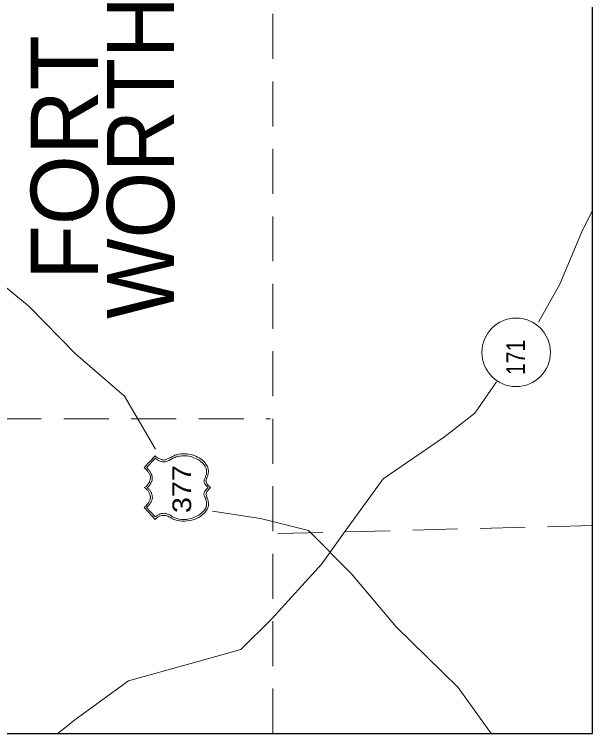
# Model space of a CAD drawing. Extents: x 2363323 to 2367082, y 6956018 to 6980837.
# Drawn here: x 2366061.2 to 2366219.2, y 6980386 to 6980582.6 of the extents above; entities that cross this region are included whole.
import ezdxf

# ---------------------------------------------------------------- set-up
doc = ezdxf.new("R2010")
doc.units = 0
doc.header["$LTSCALE"] = 4.1
doc.linetypes.add('MEDIUM_DASHED', pattern=[4.5, 3, -1.5])
doc.layers.add('62', color=7, linetype='Continuous', lineweight=13)
doc.layers.add('63', color=7, linetype='Continuous', lineweight=13)

msp = doc.modelspace()

# ---------------------------------------------------------------- linework, layer by layer
at = {"layer": '62', "linetype": 'MEDIUM_DASHED'}
for p, q in [((2366131.806, 6980385.954), (2366131.805, 6980835.548)), ((2365945.536, 6980472.004), (2366131.242, 6980472.027)), ((2366219.249, 6980442.84), (2366131.536, 6980440.635))]:
    msp.add_line(p, q, dxfattribs=at)
at = {"layer": '62'}
for p, q in [((2366078.927, 6980528.37), (2366076.924, 6980526.212)), ((2366210.249, 6980508.837), (2366204.468, 6980498.445)), ((2366187.026, 6980473.6), (2366193.011, 6980482.15)), ((2366091.302, 6980478.192), (2366099.784, 6980463.723)), ((2366178.768, 6980467.12), (2366187.026, 6980473.6))]:
    msp.add_line(p, q, dxfattribs=at)
at = {"layer": '62', "lineweight": 25}
msp.add_lwpolyline([(2365753.976, 6980385.954), (2366219.249, 6980385.954), (2366219.249, 6980835.546), (2365753.974, 6980835.546)], dxfattribs=at)
at = {"layer": '62'}
for points in [[(2366210.249, 6980508.837), (2366216.459, 6980523.668), (2366219.25, 6980528.978)], [(2366049.676, 6980516.892), (2366057.932, 6980508.726), (2366065.266, 6980502.741), (2366077.871, 6980489.824), (2366091.302, 6980478.192)], [(2366073.1, 6980385.956), (2366077.691, 6980389.758), (2366092.384, 6980400.357), (2366109.395, 6980405.127), (2366123.12, 6980408.93), (2366131.512, 6980417.21), (2366145.197, 6980432.422), (2366151.61, 6980441.355), (2366162.004, 6980455.598), (2366178.768, 6980467.12)], [(2366099.672, 6980444.528), (2366096.68, 6980447.79), (2366096.861, 6980447.97), (2366097.086, 6980448.172), (2366097.242, 6980448.352), (2366097.401, 6980448.532), (2366097.558, 6980448.712), (2366097.694, 6980448.915), (2366097.827, 6980449.095), (2366097.964, 6980449.275), (2366098.054, 6980449.455), (2366098.142, 6980449.635), (2366098.232, 6980449.836), (2366098.277, 6980450.018), (2366098.322, 6980450.22), (2366098.366, 6980450.378), (2366098.368, 6980450.58), (2366098.367, 6980450.782), (2366098.322, 6980450.918), (2366098.277, 6980451.075), (2366098.254, 6980451.255), (2366098.21, 6980451.435), (2366098.12, 6980451.616), (2366098.052, 6980451.795), (2366097.964, 6980451.952), (2366097.874, 6980452.132), (2366097.737, 6980452.314), (2366097.624, 6980452.472), (2366097.467, 6980452.628), (2366097.354, 6980452.785), (2366097.198, 6980452.922), (2366097.04, 6980453.032), (2366096.861, 6980453.122), (2366096.68, 6980453.214), (2366096.861, 6980453.325), (2366097.04, 6980453.46), (2366097.22, 6980453.572), (2366097.356, 6980453.732), (2366097.514, 6980453.866), (2366097.647, 6980454.045), (2366097.784, 6980454.225), (2366097.896, 6980454.382), (2366097.984, 6980454.564), (2366098.098, 6980454.746), (2366098.164, 6980454.948), (2366098.234, 6980455.126), (2366098.277, 6980455.353), (2366098.324, 6980455.509), (2366098.367, 6980455.734), (2366098.391, 6980455.936), (2366098.39, 6980456.094), (2366098.367, 6980456.272), (2366098.324, 6980456.43), (2366098.278, 6980456.636), (2366098.188, 6980456.792), (2366098.098, 6980456.972), (2366098.007, 6980457.13), (2366097.894, 6980457.309), (2366097.782, 6980457.465), (2366097.647, 6980457.67), (2366097.512, 6980457.828), (2366097.356, 6980458.005), (2366097.197, 6980458.166), (2366097.017, 6980458.366), (2366096.861, 6980458.502), (2366096.681, 6980458.682), (2366099.672, 6980461.946), (2366099.988, 6980461.652), (2366100.324, 6980461.359), (2366100.707, 6980461.156), (2366101.091, 6980460.999), (2366101.474, 6980460.864), (2366101.834, 6980460.796), (2366102.104, 6980460.774), (2366102.328, 6980460.798), (2366102.486, 6980460.82), (2366102.69, 6980460.91), (2366102.867, 6980460.976), (2366103.095, 6980461.066), (2366103.322, 6980461.179), (2366103.545, 6980461.293), (2366103.792, 6980461.406), (2366104.04, 6980461.539), (2366104.312, 6980461.674), (2366104.558, 6980461.81), (2366104.852, 6980461.944), (2366105.098, 6980462.056), (2366105.345, 6980462.146), (2366105.615, 6980462.214), (2366105.864, 6980462.304), (2366106.112, 6980462.326), (2366106.695, 6980462.418), (2366107.236, 6980462.462), (2366107.775, 6980462.462), (2366108.315, 6980462.416), (2366108.834, 6980462.372), (2366109.35, 6980462.258), (2366109.821, 6980462.146), (2366110.318, 6980461.988), (2366110.792, 6980461.809), (2366111.264, 6980461.584)], [(2366112.052, 6980460.414), (2366111.802, 6980460.594), (2366111.51, 6980460.795), (2366111.172, 6980460.976), (2366110.859, 6980461.134), (2366110.475, 6980461.292), (2366110.094, 6980461.449), (2366109.712, 6980461.606), (2366109.282, 6980461.719), (2366108.856, 6980461.809), (2366108.405, 6980461.876), (2366107.932, 6980461.944), (2366107.46, 6980461.942), (2366106.965, 6980461.899), (2366106.538, 6980461.852), (2366106.156, 6980461.809), (2366105.796, 6980461.719), (2366105.459, 6980461.629), (2366105.122, 6980461.496), (2366104.828, 6980461.359), (2366104.535, 6980461.246), (2366104.265, 6980461.089), (2366103.995, 6980460.909), (2366103.772, 6980460.796), (2366103.524, 6980460.662), (2366103.276, 6980460.549), (2366103.028, 6980460.436), (2366102.778, 6980460.369), (2366102.531, 6980460.302), (2366102.261, 6980460.256), (2366101.946, 6980460.256), (2366101.607, 6980460.302), (2366101.27, 6980460.369), (2366100.932, 6980460.459), (2366100.596, 6980460.596), (2366100.281, 6980460.796), (2366099.987, 6980461), (2366099.696, 6980461.248), (2366097.288, 6980458.659), (2366097.468, 6980458.502), (2366097.626, 6980458.366), (2366097.782, 6980458.209), (2366097.94, 6980458.052), (2366098.076, 6980457.873), (2366098.211, 6980457.692), (2366098.322, 6980457.513), (2366098.434, 6980457.332), (2366098.524, 6980457.129), (2366098.637, 6980456.949), (2366098.706, 6980456.746), (2366098.751, 6980456.589), (2366098.817, 6980456.388), (2366098.841, 6980456.229), (2366098.862, 6980456.094), (2366098.884, 6980455.935), (2366098.864, 6980455.779), (2366098.864, 6980455.576), (2366098.84, 6980455.396), (2366098.817, 6980455.216), (2366098.751, 6980455.014), (2366098.682, 6980454.856), (2366098.614, 6980454.654), (2366098.524, 6980454.474), (2366098.434, 6980454.316), (2366098.344, 6980454.112), (2366098.232, 6980453.956), (2366098.097, 6980453.798), (2366097.984, 6980453.618), (2366097.827, 6980453.505), (2366097.671, 6980453.348), (2366097.491, 6980453.212), (2366097.67, 6980453.078), (2366097.827, 6980452.965), (2366097.941, 6980452.808), (2366098.076, 6980452.674), (2366098.164, 6980452.538), (2366098.277, 6980452.404), (2366098.39, 6980452.222), (2366098.48, 6980452.108), (2366098.547, 6980451.93), (2366098.637, 6980451.772), (2366098.684, 6980451.616), (2366098.75, 6980451.458), (2366098.772, 6980451.298), (2366098.84, 6980451.144), (2366098.864, 6980450.964), (2366098.886, 6980450.805), (2366098.907, 6980450.625), (2366098.907, 6980450.4), (2366098.862, 6980450.22), (2366098.817, 6980449.996), (2366098.75, 6980449.794), (2366098.66, 6980449.568), (2366098.57, 6980449.365), (2366098.457, 6980449.185), (2366098.344, 6980448.982), (2366098.21, 6980448.759), (2366098.097, 6980448.578), (2366097.941, 6980448.42), (2366097.782, 6980448.218), (2366097.626, 6980448.06)], [(2366111.264, 6980461.584), (2366111.692, 6980461.36), (2366112.096, 6980461.066), (2366112.5, 6980460.776), (2366112.86, 6980460.414), (2366113.22, 6980460.054), (2366113.558, 6980459.672), (2366113.716, 6980459.446), (2366113.828, 6980459.244), (2366113.94, 6980458.996), (2366114.032, 6980458.772), (2366114.12, 6980458.569), (2366114.142, 6980458.344), (2366114.21, 6980458.096), (2366114.234, 6980457.894), (2366114.255, 6980457.669), (2366114.234, 6980457.444), (2366114.21, 6980457.242), (2366114.188, 6980457.04), (2366114.12, 6980456.814), (2366114.098, 6980456.656), (2366114.032, 6980456.454), (2366113.94, 6980456.274), (2366113.872, 6980456.116), (2366113.829, 6980455.938), (2366113.739, 6980455.78), (2366113.672, 6980455.623), (2366113.648, 6980455.464), (2366113.604, 6980455.306), (2366113.558, 6980455.126), (2366113.58, 6980454.946), (2366113.625, 6980454.766), (2366113.692, 6980454.586), (2366113.805, 6980454.382), (2366113.919, 6980454.202), (2366114.099, 6980453.955), (2366114.278, 6980453.73), (2366114.548, 6980453.505), (2366114.84, 6980453.212), (2366114.572, 6980452.965), (2366114.346, 6980452.718), (2366114.122, 6980452.515), (2366113.986, 6980452.312), (2366113.828, 6980452.132), (2366113.738, 6980451.954), (2366113.67, 6980451.795), (2366113.625, 6980451.638), (2366113.602, 6980451.525), (2366113.602, 6980451.346), (2366113.604, 6980451.232), (2366113.67, 6980451.075), (2366113.694, 6980450.94), (2366113.715, 6980450.805), (2366113.805, 6980450.649), (2366113.85, 6980450.488), (2366113.918, 6980450.378), (2366113.962, 6980450.198), (2366114.032, 6980450.018), (2366114.098, 6980449.839), (2366114.122, 6980449.635), (2366114.142, 6980449.455), (2366114.21, 6980449.252), (2366114.232, 6980449.052), (2366114.234, 6980448.825), (2366114.232, 6980448.645), (2366114.232, 6980448.42), (2366114.212, 6980448.172), (2366114.142, 6980447.97), (2366114.098, 6980447.745), (2366113.986, 6980447.52), (2366113.874, 6980447.296), (2366113.558, 6980446.778), (2366113.128, 6980446.282), (2366112.658, 6980445.832), (2366112.14, 6980445.428), (2366111.578, 6980445.068), (2366111.016, 6980444.775), (2366110.385, 6980444.55), (2366109.734, 6980444.348), (2366109.08, 6980444.214), (2366108.429, 6980444.122), (2366107.775, 6980444.055), (2366107.122, 6980444.056), (2366106.448, 6980444.122), (2366105.84, 6980444.235), (2366105.188, 6980444.415), (2366104.625, 6980444.638), (2366104.402, 6980444.73), (2366104.154, 6980444.842), (2366103.929, 6980444.976), (2366103.682, 6980445.135), (2366103.41, 6980445.248), (2366103.14, 6980445.382), (2366102.846, 6980445.518), (2366102.555, 6980445.585), (2366102.237, 6980445.63), (2366101.901, 6980445.63), (2366101.562, 6980445.632), (2366101.224, 6980445.518), (2366100.863, 6980445.405), (2366100.461, 6980445.202)], [(2366097.332, 6980447.792), (2366099.694, 6980445.225), (2366100.054, 6980445.518), (2366100.438, 6980445.72), (2366100.754, 6980445.9), (2366101.067, 6980446.035), (2366101.404, 6980446.125), (2366101.72, 6980446.17), (2366101.991, 6980446.215), (2366102.284, 6980446.172), (2366102.576, 6980446.126), (2366102.846, 6980446.058), (2366103.142, 6980445.968), (2366103.41, 6980445.855), (2366103.658, 6980445.742), (2366103.928, 6980445.584), (2366104.175, 6980445.429), (2366104.445, 6980445.27), (2366105.032, 6980444.978), (2366105.66, 6980444.776), (2366106.269, 6980444.618), (2366106.942, 6980444.55), (2366107.616, 6980444.528), (2366108.272, 6980444.55), (2366108.945, 6980444.661), (2366109.575, 6980444.818), (2366110.204, 6980445.022), (2366110.835, 6980445.294), (2366111.398, 6980445.584), (2366111.939, 6980445.945), (2366112.41, 6980446.328), (2366112.86, 6980446.754), (2366113.22, 6980447.229), (2366113.558, 6980447.722), (2366113.58, 6980447.836), (2366113.648, 6980447.949), (2366113.67, 6980448.104), (2366113.672, 6980448.285), (2366113.694, 6980448.442), (2366113.715, 6980448.6), (2366113.715, 6980448.782), (2366113.692, 6980448.982), (2366113.67, 6980449.164), (2366113.67, 6980449.342), (2366113.625, 6980449.524), (2366113.602, 6980449.702), (2366113.558, 6980449.882), (2366113.512, 6980450.04), (2366113.445, 6980450.198), (2366113.424, 6980450.332), (2366113.332, 6980450.49), (2366113.265, 6980450.625), (2366113.198, 6980450.76), (2366113.132, 6980450.896), (2366113.086, 6980451.075), (2366113.062, 6980451.188), (2366113.018, 6980451.345), (2366113.018, 6980451.526), (2366113.062, 6980451.682), (2366113.108, 6980451.885), (2366113.176, 6980452.065), (2366113.288, 6980452.224), (2366113.422, 6980452.449), (2366113.648, 6980452.674), (2366113.872, 6980452.942), (2366114.142, 6980453.19), (2366113.85, 6980453.505), (2366113.602, 6980453.776), (2366113.422, 6980454), (2366113.265, 6980454.248), (2366113.175, 6980454.472), (2366113.108, 6980454.652), (2366113.064, 6980454.856), (2366113.062, 6980455.058), (2366113.062, 6980455.239), (2366113.108, 6980455.396), (2366113.176, 6980455.576), (2366113.22, 6980455.756), (2366113.31, 6980455.936), (2366113.402, 6980456.116), (2366113.445, 6980456.296), (2366113.558, 6980456.498), (2366113.602, 6980456.702), (2366113.672, 6980456.928), (2366113.694, 6980457.129), (2366113.716, 6980457.33), (2366113.715, 6980457.556), (2366113.716, 6980457.782), (2366113.694, 6980457.986), (2366113.67, 6980458.209), (2366113.604, 6980458.434), (2366113.558, 6980458.638), (2366113.422, 6980458.84), (2366113.332, 6980459.064), (2366113.198, 6980459.246), (2366113.064, 6980459.469), (2366112.882, 6980459.672), (2366112.682, 6980459.874), (2366112.522, 6980460.056), (2366112.275, 6980460.213), (2366112.052, 6980460.414)], [(2366097.626, 6980448.06), (2366097.467, 6980447.925), (2366097.332, 6980447.792)], [(2366115.359, 6980446.8), (2366128.43, 6980444.822), (2366141.55, 6980441.49), (2366153.252, 6980429.766), (2366165.558, 6980415.117), (2366182.458, 6980398.58), (2366191.482, 6980385.954)], [(2366100.461, 6980445.202), (2366100.077, 6980444.912), (2366099.672, 6980444.528)]]:
    msp.add_lwpolyline(points, dxfattribs=at)
msp.add_circle((2366198.354, 6980490.209), 9.364, dxfattribs=at)
at = {"layer": '63', "linetype": 'MEDIUM_DASHED'}
for p, q in [((2366131.806, 6980385.954), (2366131.805, 6980835.548)), ((2365945.536, 6980472.004), (2366131.242, 6980472.027)), ((2366219.249, 6980442.84), (2366131.536, 6980440.635))]:
    msp.add_line(p, q, dxfattribs=at)
at = {"layer": '63'}
for p, q in [((2366078.927, 6980528.37), (2366076.924, 6980526.212)), ((2366210.249, 6980508.837), (2366204.468, 6980498.445)), ((2366187.026, 6980473.6), (2366193.011, 6980482.15)), ((2366091.302, 6980478.192), (2366099.784, 6980463.723)), ((2366178.768, 6980467.12), (2366187.026, 6980473.6))]:
    msp.add_line(p, q, dxfattribs=at)
at = {"layer": '63', "lineweight": 25}
msp.add_lwpolyline([(2365753.976, 6980385.954), (2366219.249, 6980385.954), (2366219.249, 6980835.546), (2365753.974, 6980835.546)], dxfattribs=at)
at = {"layer": '63'}
for points in [[(2366210.249, 6980508.837), (2366216.459, 6980523.668), (2366219.25, 6980528.978)], [(2366049.676, 6980516.892), (2366057.932, 6980508.726), (2366065.266, 6980502.741), (2366077.871, 6980489.824), (2366091.302, 6980478.192)], [(2366073.1, 6980385.956), (2366077.691, 6980389.758), (2366092.384, 6980400.357), (2366109.395, 6980405.127), (2366123.12, 6980408.93), (2366131.512, 6980417.21), (2366145.197, 6980432.422), (2366151.61, 6980441.355), (2366162.004, 6980455.598), (2366178.768, 6980467.12)], [(2366099.672, 6980444.528), (2366096.68, 6980447.79), (2366096.861, 6980447.97), (2366097.086, 6980448.172), (2366097.242, 6980448.352), (2366097.401, 6980448.532), (2366097.558, 6980448.712), (2366097.694, 6980448.915), (2366097.827, 6980449.095), (2366097.964, 6980449.275), (2366098.054, 6980449.455), (2366098.142, 6980449.635), (2366098.232, 6980449.836), (2366098.277, 6980450.018), (2366098.322, 6980450.22), (2366098.366, 6980450.378), (2366098.368, 6980450.58), (2366098.367, 6980450.782), (2366098.322, 6980450.918), (2366098.277, 6980451.075), (2366098.254, 6980451.255), (2366098.21, 6980451.435), (2366098.12, 6980451.616), (2366098.052, 6980451.795), (2366097.964, 6980451.952), (2366097.874, 6980452.132), (2366097.737, 6980452.314), (2366097.624, 6980452.472), (2366097.467, 6980452.628), (2366097.354, 6980452.785), (2366097.198, 6980452.922), (2366097.04, 6980453.032), (2366096.861, 6980453.122), (2366096.68, 6980453.214), (2366096.861, 6980453.325), (2366097.04, 6980453.46), (2366097.22, 6980453.572), (2366097.356, 6980453.732), (2366097.514, 6980453.866), (2366097.647, 6980454.045), (2366097.784, 6980454.225), (2366097.896, 6980454.382), (2366097.984, 6980454.564), (2366098.098, 6980454.746), (2366098.164, 6980454.948), (2366098.234, 6980455.126), (2366098.277, 6980455.353), (2366098.324, 6980455.509), (2366098.367, 6980455.734), (2366098.391, 6980455.936), (2366098.39, 6980456.094), (2366098.367, 6980456.272), (2366098.324, 6980456.43), (2366098.278, 6980456.636), (2366098.188, 6980456.792), (2366098.098, 6980456.972), (2366098.007, 6980457.13), (2366097.894, 6980457.309), (2366097.782, 6980457.465), (2366097.647, 6980457.67), (2366097.512, 6980457.828), (2366097.356, 6980458.005), (2366097.197, 6980458.166), (2366097.017, 6980458.366), (2366096.861, 6980458.502), (2366096.681, 6980458.682), (2366099.672, 6980461.946), (2366099.988, 6980461.652), (2366100.324, 6980461.359), (2366100.707, 6980461.156), (2366101.091, 6980460.999), (2366101.474, 6980460.864), (2366101.834, 6980460.796), (2366102.104, 6980460.774), (2366102.328, 6980460.798), (2366102.486, 6980460.82), (2366102.69, 6980460.91), (2366102.867, 6980460.976), (2366103.095, 6980461.066), (2366103.322, 6980461.179), (2366103.545, 6980461.293), (2366103.792, 6980461.406), (2366104.04, 6980461.539), (2366104.312, 6980461.674), (2366104.558, 6980461.81), (2366104.852, 6980461.944), (2366105.098, 6980462.056), (2366105.345, 6980462.146), (2366105.615, 6980462.214), (2366105.864, 6980462.304), (2366106.112, 6980462.326), (2366106.695, 6980462.418), (2366107.236, 6980462.462), (2366107.775, 6980462.462), (2366108.315, 6980462.416), (2366108.834, 6980462.372), (2366109.35, 6980462.258), (2366109.821, 6980462.146), (2366110.318, 6980461.988), (2366110.792, 6980461.809), (2366111.264, 6980461.584)], [(2366112.052, 6980460.414), (2366111.802, 6980460.594), (2366111.51, 6980460.795), (2366111.172, 6980460.976), (2366110.859, 6980461.134), (2366110.475, 6980461.292), (2366110.094, 6980461.449), (2366109.712, 6980461.606), (2366109.282, 6980461.719), (2366108.856, 6980461.809), (2366108.405, 6980461.876), (2366107.932, 6980461.944), (2366107.46, 6980461.942), (2366106.965, 6980461.899), (2366106.538, 6980461.852), (2366106.156, 6980461.809), (2366105.796, 6980461.719), (2366105.459, 6980461.629), (2366105.122, 6980461.496), (2366104.828, 6980461.359), (2366104.535, 6980461.246), (2366104.265, 6980461.089), (2366103.995, 6980460.909), (2366103.772, 6980460.796), (2366103.524, 6980460.662), (2366103.276, 6980460.549), (2366103.028, 6980460.436), (2366102.778, 6980460.369), (2366102.531, 6980460.302), (2366102.261, 6980460.256), (2366101.946, 6980460.256), (2366101.607, 6980460.302), (2366101.27, 6980460.369), (2366100.932, 6980460.459), (2366100.596, 6980460.596), (2366100.281, 6980460.796), (2366099.987, 6980461), (2366099.696, 6980461.248), (2366097.288, 6980458.659), (2366097.468, 6980458.502), (2366097.626, 6980458.366), (2366097.782, 6980458.209), (2366097.94, 6980458.052), (2366098.076, 6980457.873), (2366098.211, 6980457.692), (2366098.322, 6980457.513), (2366098.434, 6980457.332), (2366098.524, 6980457.129), (2366098.637, 6980456.949), (2366098.706, 6980456.746), (2366098.751, 6980456.589), (2366098.817, 6980456.388), (2366098.841, 6980456.229), (2366098.862, 6980456.094), (2366098.884, 6980455.935), (2366098.864, 6980455.779), (2366098.864, 6980455.576), (2366098.84, 6980455.396), (2366098.817, 6980455.216), (2366098.751, 6980455.014), (2366098.682, 6980454.856), (2366098.614, 6980454.654), (2366098.524, 6980454.474), (2366098.434, 6980454.316), (2366098.344, 6980454.112), (2366098.232, 6980453.956), (2366098.097, 6980453.798), (2366097.984, 6980453.618), (2366097.827, 6980453.505), (2366097.671, 6980453.348), (2366097.491, 6980453.212), (2366097.67, 6980453.078), (2366097.827, 6980452.965), (2366097.941, 6980452.808), (2366098.076, 6980452.674), (2366098.164, 6980452.538), (2366098.277, 6980452.404), (2366098.39, 6980452.222), (2366098.48, 6980452.108), (2366098.547, 6980451.93), (2366098.637, 6980451.772), (2366098.684, 6980451.616), (2366098.75, 6980451.458), (2366098.772, 6980451.298), (2366098.84, 6980451.144), (2366098.864, 6980450.964), (2366098.886, 6980450.805), (2366098.907, 6980450.625), (2366098.907, 6980450.4), (2366098.862, 6980450.22), (2366098.817, 6980449.996), (2366098.75, 6980449.794), (2366098.66, 6980449.568), (2366098.57, 6980449.365), (2366098.457, 6980449.185), (2366098.344, 6980448.982), (2366098.21, 6980448.759), (2366098.097, 6980448.578), (2366097.941, 6980448.42), (2366097.782, 6980448.218), (2366097.626, 6980448.06)], [(2366111.264, 6980461.584), (2366111.692, 6980461.36), (2366112.096, 6980461.066), (2366112.5, 6980460.776), (2366112.86, 6980460.414), (2366113.22, 6980460.054), (2366113.558, 6980459.672), (2366113.716, 6980459.446), (2366113.828, 6980459.244), (2366113.94, 6980458.996), (2366114.032, 6980458.772), (2366114.12, 6980458.569), (2366114.142, 6980458.344), (2366114.21, 6980458.096), (2366114.234, 6980457.894), (2366114.255, 6980457.669), (2366114.234, 6980457.444), (2366114.21, 6980457.242), (2366114.188, 6980457.04), (2366114.12, 6980456.814), (2366114.098, 6980456.656), (2366114.032, 6980456.454), (2366113.94, 6980456.274), (2366113.872, 6980456.116), (2366113.829, 6980455.938), (2366113.739, 6980455.78), (2366113.672, 6980455.623), (2366113.648, 6980455.464), (2366113.604, 6980455.306), (2366113.558, 6980455.126), (2366113.58, 6980454.946), (2366113.625, 6980454.766), (2366113.692, 6980454.586), (2366113.805, 6980454.382), (2366113.919, 6980454.202), (2366114.099, 6980453.955), (2366114.278, 6980453.73), (2366114.548, 6980453.505), (2366114.84, 6980453.212), (2366114.572, 6980452.965), (2366114.346, 6980452.718), (2366114.122, 6980452.515), (2366113.986, 6980452.312), (2366113.828, 6980452.132), (2366113.738, 6980451.954), (2366113.67, 6980451.795), (2366113.625, 6980451.638), (2366113.602, 6980451.525), (2366113.602, 6980451.346), (2366113.604, 6980451.232), (2366113.67, 6980451.075), (2366113.694, 6980450.94), (2366113.715, 6980450.805), (2366113.805, 6980450.649), (2366113.85, 6980450.488), (2366113.918, 6980450.378), (2366113.962, 6980450.198), (2366114.032, 6980450.018), (2366114.098, 6980449.839), (2366114.122, 6980449.635), (2366114.142, 6980449.455), (2366114.21, 6980449.252), (2366114.232, 6980449.052), (2366114.234, 6980448.825), (2366114.232, 6980448.645), (2366114.232, 6980448.42), (2366114.212, 6980448.172), (2366114.142, 6980447.97), (2366114.098, 6980447.745), (2366113.986, 6980447.52), (2366113.874, 6980447.296), (2366113.558, 6980446.778), (2366113.128, 6980446.282), (2366112.658, 6980445.832), (2366112.14, 6980445.428), (2366111.578, 6980445.068), (2366111.016, 6980444.775), (2366110.385, 6980444.55), (2366109.734, 6980444.348), (2366109.08, 6980444.214), (2366108.429, 6980444.122), (2366107.775, 6980444.055), (2366107.122, 6980444.056), (2366106.448, 6980444.122), (2366105.84, 6980444.235), (2366105.188, 6980444.415), (2366104.625, 6980444.638), (2366104.402, 6980444.73), (2366104.154, 6980444.842), (2366103.929, 6980444.976), (2366103.682, 6980445.135), (2366103.41, 6980445.248), (2366103.14, 6980445.382), (2366102.846, 6980445.518), (2366102.555, 6980445.585), (2366102.237, 6980445.63), (2366101.901, 6980445.63), (2366101.562, 6980445.632), (2366101.224, 6980445.518), (2366100.863, 6980445.405), (2366100.461, 6980445.202)], [(2366097.332, 6980447.792), (2366099.694, 6980445.225), (2366100.054, 6980445.518), (2366100.438, 6980445.72), (2366100.754, 6980445.9), (2366101.067, 6980446.035), (2366101.404, 6980446.125), (2366101.72, 6980446.17), (2366101.991, 6980446.215), (2366102.284, 6980446.172), (2366102.576, 6980446.126), (2366102.846, 6980446.058), (2366103.142, 6980445.968), (2366103.41, 6980445.855), (2366103.658, 6980445.742), (2366103.928, 6980445.584), (2366104.175, 6980445.429), (2366104.445, 6980445.27), (2366105.032, 6980444.978), (2366105.66, 6980444.776), (2366106.269, 6980444.618), (2366106.942, 6980444.55), (2366107.616, 6980444.528), (2366108.272, 6980444.55), (2366108.945, 6980444.661), (2366109.575, 6980444.818), (2366110.204, 6980445.022), (2366110.835, 6980445.294), (2366111.398, 6980445.584), (2366111.939, 6980445.945), (2366112.41, 6980446.328), (2366112.86, 6980446.754), (2366113.22, 6980447.229), (2366113.558, 6980447.722), (2366113.58, 6980447.836), (2366113.648, 6980447.949), (2366113.67, 6980448.104), (2366113.672, 6980448.285), (2366113.694, 6980448.442), (2366113.715, 6980448.6), (2366113.715, 6980448.782), (2366113.692, 6980448.982), (2366113.67, 6980449.164), (2366113.67, 6980449.342), (2366113.625, 6980449.524), (2366113.602, 6980449.702), (2366113.558, 6980449.882), (2366113.512, 6980450.04), (2366113.445, 6980450.198), (2366113.424, 6980450.332), (2366113.332, 6980450.49), (2366113.265, 6980450.625), (2366113.198, 6980450.76), (2366113.132, 6980450.896), (2366113.086, 6980451.075), (2366113.062, 6980451.188), (2366113.018, 6980451.345), (2366113.018, 6980451.526), (2366113.062, 6980451.682), (2366113.108, 6980451.885), (2366113.176, 6980452.065), (2366113.288, 6980452.224), (2366113.422, 6980452.449), (2366113.648, 6980452.674), (2366113.872, 6980452.942), (2366114.142, 6980453.19), (2366113.85, 6980453.505), (2366113.602, 6980453.776), (2366113.422, 6980454), (2366113.265, 6980454.248), (2366113.175, 6980454.472), (2366113.108, 6980454.652), (2366113.064, 6980454.856), (2366113.062, 6980455.058), (2366113.062, 6980455.239), (2366113.108, 6980455.396), (2366113.176, 6980455.576), (2366113.22, 6980455.756), (2366113.31, 6980455.936), (2366113.402, 6980456.116), (2366113.445, 6980456.296), (2366113.558, 6980456.498), (2366113.602, 6980456.702), (2366113.672, 6980456.928), (2366113.694, 6980457.129), (2366113.716, 6980457.33), (2366113.715, 6980457.556), (2366113.716, 6980457.782), (2366113.694, 6980457.986), (2366113.67, 6980458.209), (2366113.604, 6980458.434), (2366113.558, 6980458.638), (2366113.422, 6980458.84), (2366113.332, 6980459.064), (2366113.198, 6980459.246), (2366113.064, 6980459.469), (2366112.882, 6980459.672), (2366112.682, 6980459.874), (2366112.522, 6980460.056), (2366112.275, 6980460.213), (2366112.052, 6980460.414)], [(2366097.626, 6980448.06), (2366097.467, 6980447.925), (2366097.332, 6980447.792)], [(2366115.359, 6980446.8), (2366128.43, 6980444.822), (2366141.55, 6980441.49), (2366153.252, 6980429.766), (2366165.558, 6980415.117), (2366182.458, 6980398.58), (2366191.482, 6980385.954)], [(2366100.461, 6980445.202), (2366100.077, 6980444.912), (2366099.672, 6980444.528)]]:
    msp.add_lwpolyline(points, dxfattribs=at)
msp.add_circle((2366198.354, 6980490.209), 9.364, dxfattribs=at)

# ---------------------------------------------------------------- texts
at = {"layer": '62'}
for s, height, width, p in [('WORTH', 18.39, 0.95, (2366104.871, 6980499.342)), ('171', 5.099, 0.85, (2366200.75, 6980483.996)), ('377', 5.099, 1.15, (2366109.508, 6980446.26))]:
    msp.add_text(s, height=height, rotation=90, dxfattribs=dict(at, width=width)).set_placement(p)
msp.add_text('FORT', height=18.39, rotation=90, dxfattribs=at).set_placement((2366084.057, 6980509.986))
at = {"layer": '63'}
for s, height, width, p in [('WORTH', 18.39, 0.95, (2366104.871, 6980499.342)), ('171', 5.099, 0.85, (2366200.75, 6980483.996)), ('377', 5.099, 1.15, (2366109.508, 6980446.26))]:
    msp.add_text(s, height=height, rotation=90, dxfattribs=dict(at, width=width)).set_placement(p)
msp.add_text('FORT', height=18.39, rotation=90, dxfattribs=at).set_placement((2366084.057, 6980509.986))

doc.saveas('drawing.dxf')
